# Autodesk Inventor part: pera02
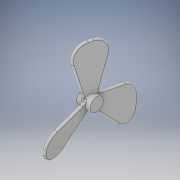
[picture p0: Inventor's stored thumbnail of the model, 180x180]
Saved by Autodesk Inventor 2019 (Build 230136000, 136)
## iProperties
Created: 2020-08
Part Number: pera02
Material: 一般
Document SubType Name: Modeling
Designer: kikut
Density: 1 g/cm^3
Appearance: 既定
Author: kikut
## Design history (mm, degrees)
sketch "スケッチ3"
  geometry: L1 (0.001, 0.01)-(-0.005, -0.009); L2 (-0.005, -0.009)-(-0.001, -0.01); L3 (-0.001, -0.01)-(0.005, 0.009); L4 (0.005, 0.009)-(0.001, 0.01); L5 (0.001, 0.01)-(-0.001, -0.01); L6 (-0.005, -0.009)-(0.005, 0.009); L7 (0, -0.014)-(0, 0.014) reference; 3 further points
  constraints: 12 end point, 3 midpoint, 2 parallel, 1 coincident, 1 perpendicular
  dimensions: "d8" = 0.02 distance of L1.start L1.end; "d9" = 165 deg angle of L7 L1; "d19" = 0.004 distance of L3.end L1.start
extrude "押し出し1" new body sketch "スケッチ3" distance "d10" = 0.079; taper "d11" = 0 deg
sketch "スケッチ6"
  geometry: L1 (-0.02, 0)-(-0.02, 0.079) reference; L2 (-0.02, 0.01)-(-0.04, 0.079); L3 (-0.04, 0.079)-(0.02, 0.079); L4 (0.02, 0.079)-(0, 0.01); L5 (0, 0)-(0, 0.079) reference; L6 (-0.02, 0.01)-(0, 0.01); L7 (-0.02, 0)-(0, 0) reference; 1 further point
  constraints: 8 end point, 2 perpendicular, 2 point on line
  dimensions: "d20" = 0.01 distance between parallel lines of L6 L7; "d21" = 0.06 distance of L2.end L3.end; "d22" = 0.02 distance from line of L2.end L1
extrude "押し出し3" join sketch "スケッチ6" distance "d23" = 0.004; taper "d24" = 0 deg
fillet "フィレット2" dims "d25" = 0.02
fillet "フィレット3" dims "d26" = 0.02
pattern_circular "円形状パターン2" dims "d28" = 360 deg
sketch "スケッチ7"
  geometry: L1 (0, 0)-(0, 0.009) reference; C1 r 0.01 at (0, 0)
  constraints: 1 centre point, 1 coincident
  dimensions: "d30" = 0.02 diameter of C1
extrude "押し出し4" join sketch "スケッチ7" stored distance "d31" = 0.02; taper "d32" = 0 deg
fillet "フィレット4" dims "d33" = 0.002
node "ソリッド1"
